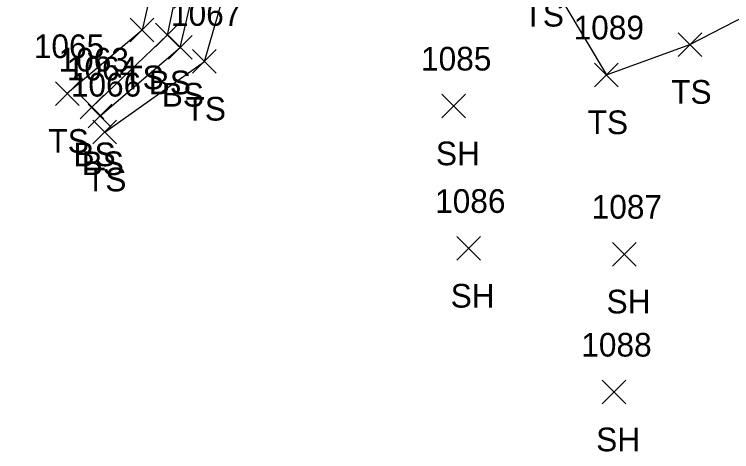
# Model space of a CAD drawing. Extents: x 1514253 to 1516033, y 782541 to 785002.
# Drawn here: x 1515259.8 to 1515320.5, y 782590.7 to 782627.7 of the extents above; entities that cross this region are included whole.
import ezdxf

# ---------------------------------------------------------------- set-up
doc = ezdxf.new("R2010")
doc.units = 0
for name, color, linetype in [('L_A', 7, 'Continuous'), ('L_I', 7, 'Continuous'), ('L_TIC', 7, 'Continuous'), ('LELB', 7, 'Continuous')]:
    doc.layers.add(name, color=color, linetype=linetype)

msp = doc.modelspace()

# ---------------------------------------------------------------- linework, layer by layer
at = {"layer": 'L_TIC'}
for points in [[(1515269.641, 782625.326), (1515271.641, 782627.326)], [(1515271.641, 782625.326), (1515269.641, 782627.326)], [(1515271.765, 782624.903), (1515273.765, 782626.903)], [(1515273.765, 782624.903), (1515271.765, 782626.903)], [(1515315.95, 782624.103), (1515317.95, 782626.103)], [(1515317.95, 782624.103), (1515315.95, 782626.103)], [(1515272.864, 782623.863), (1515274.864, 782625.863)], [(1515274.864, 782623.863), (1515272.864, 782625.863)], [(1515274.905, 782622.682), (1515276.905, 782624.682)], [(1515276.905, 782622.682), (1515274.905, 782624.682)], [(1515308.893, 782621.536), (1515310.893, 782623.536)], [(1515310.893, 782621.536), (1515308.893, 782623.536)], [(1515263.311, 782619.96), (1515265.311, 782621.96)], [(1515265.311, 782619.96), (1515263.311, 782621.96)], [(1515265.399, 782618.826), (1515267.399, 782620.826)], [(1515267.399, 782618.826), (1515265.399, 782620.826)], [(1515295.989, 782618.909), (1515297.989, 782620.909)], [(1515297.989, 782618.909), (1515295.989, 782620.909)], [(1515266.096, 782618.076), (1515268.096, 782620.076)], [(1515268.096, 782618.076), (1515266.096, 782620.076)], [(1515266.493, 782616.708), (1515268.493, 782618.708)], [(1515268.493, 782616.708), (1515266.493, 782618.708)], [(1515297.237, 782606.887), (1515299.237, 782608.887)], [(1515299.237, 782606.887), (1515297.237, 782608.887)], [(1515310.413, 782606.396), (1515312.413, 782608.396)], [(1515312.413, 782606.396), (1515310.413, 782608.396)], [(1515309.534, 782594.751), (1515311.534, 782596.751)], [(1515311.534, 782594.751), (1515309.534, 782596.751)]]:
    msp.add_lwpolyline(points, dxfattribs=at)
at = {"layer": 'LELB'}
for points in [[(1515272.163, 782648.844), (1515275.745, 782643.731), (1515274.9, 782636.131), (1515272.765, 782625.903), (1515266.399, 782619.826)], [(1515198.67, 782646.535), (1515234.653, 782643.768), (1515272.442, 782643.038), (1515272.72, 782635.52), (1515270.641, 782626.326), (1515264.311, 782620.96)], [(1515267.096, 782619.076), (1515273.864, 782624.863), (1515276.319, 782635.308), (1515279.925, 782643.508), (1515284.876, 782645.286), (1515293.699, 782642.978), (1515298.257, 782639.773), (1515306.339, 782638.14), (1515312.767, 782632.766), (1515316.681, 782633.039), (1515323.367, 782638.781), (1515328.746, 782636.685), (1515333.036, 782633.949)], [(1515267.493, 782617.708), (1515275.905, 782623.682), (1515279.076, 782634.626), (1515280.627, 782640.948), (1515290.641, 782638.315), (1515296.789, 782634.635), (1515304.473, 782631.621), (1515309.893, 782622.536), (1515316.95, 782625.103), (1515323.664, 782628.572), (1515323.948, 782631.832), (1515325.669, 782634.817), (1515329.658, 782632.505), (1515330.558, 782622.703), (1515325.128, 782602.902)]]:
    msp.add_lwpolyline(points, dxfattribs=at)

# ---------------------------------------------------------------- texts
at = {"layer": 'L_A'}
for s, p in [('TS', (1515302.883, 782626.621)), ('TS', (1515269.05, 782621.326)), ('BS', (1515271.206, 782620.903)), ('BS', (1515272.305, 782619.863)), ('TS', (1515315.359, 782620.103)), ('TS', (1515274.314, 782618.682)), ('TS', (1515308.302, 782617.536)), ('TS', (1515262.721, 782615.96)), ('BS', (1515264.84, 782614.826)), ('SH', (1515295.477, 782614.909)), ('BS', (1515265.537, 782614.076)), ('TS', (1515265.902, 782612.708)), ('SH', (1515296.725, 782602.887)), ('SH', (1515309.901, 782602.396)), ('SH', (1515309.022, 782590.751))]:
    msp.add_text(s, height=2, dxfattribs=at).set_placement(p)
at = {"layer": 'L_I'}
for s, p in [('1067', (1515273.086, 782626.682)), ('1089', (1515307.113, 782625.536)), ('1065', (1515261.492, 782623.96)), ('1085', (1515294.217, 782622.909)), ('1063', (1515263.58, 782622.826)), ('1064', (1515264.277, 782622.076)), ('1066', (1515264.619, 782620.708)), ('1086', (1515295.41, 782610.887)), ('1087', (1515308.641, 782610.396)), ('1088', (1515307.762, 782598.751))]:
    msp.add_text(s, height=2, dxfattribs=at).set_placement(p)

doc.saveas('drawing.dxf')
